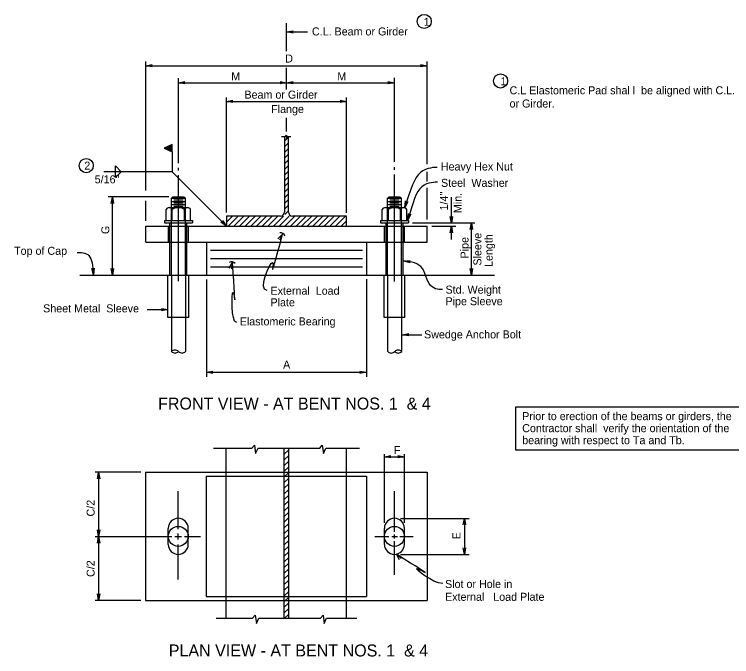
# Model space of a CAD drawing. Extents: x 113 to 232, y -103 to -27.
# Drawn here: x 116.48 to 123.95, y -74.62 to -67.93 of the extents above; entities that cross this region are included whole.
import ezdxf

# ---------------------------------------------------------------- set-up
doc = ezdxf.new("R2010")
doc.units = 0
for name, color, linetype in [('1', 7, 'Continuous'), ('B_Dimension', 7, 'Continuous'), ('B_Title Text', 7, 'Continuous')]:
    doc.layers.add(name, color=color, linetype=linetype)

msp = doc.modelspace()

# ---------------------------------------------------------------- linework, layer by layer
at = {"layer": '1'}
for p, q in [((119.3174, -68.3191), (119.3174, -68.0268)), ((119.3174, -68.118), (119.5347, -68.118)), ((117.8502, -69.7675), (117.8502, -68.4251)), ((120.7802, -69.4948), (120.7802, -68.4251)), ((117.8502, -68.4698), (120.7802, -68.4698)), ((119.3174, -68.717), (119.3174, -68.49)), ((118.1902, -69.4816), (118.1902, -68.5975)), ((120.4402, -69.4709), (120.4402, -68.5966)), ((118.1902, -68.6466), (119.3174, -68.6466)), ((119.3174, -68.6466), (120.4402, -68.6466)), ((118.6902, -69.9965), (118.6902, -68.8018)), ((119.9402, -69.9989), (119.9402, -68.8018)), ((118.6902, -68.8413), (119.9416, -68.8413)), ((119.3174, -69.1529), (119.3174, -69.0125)), ((119.307, -69.2073), (119.3149, -69.1932)), ((119.3149, -69.1932), (119.3149, -69.2263)), ((119.2635, -69.2073), (119.307, -69.2073)), ((119.2944, -69.2073), (119.2944, -69.9915)), ((119.3149, -69.2263), (119.3211, -69.2073)), ((119.3211, -69.2073), (119.3614, -69.2073)), ((119.3359, -69.9915), (119.3359, -69.2073)), ((118.1246, -69.2896), (118.0436, -69.3274)), ((118.0436, -69.3274), (118.1246, -69.365)), ((118.1246, -69.2896), (118.1246, -69.289)), ((118.1246, -69.365), (118.1246, -69.2896)), ((118.1246, -69.365), (118.1246, -69.3955)), ((118.1246, -69.3955), (118.1246, -69.5718)), ((118.1246, -69.5718), (117.4154, -69.5718)), ((117.5347, -69.6308), (117.5347, -69.5128)), ((117.5347, -69.5128), (117.5937, -69.5718)), ((117.5937, -69.5718), (117.5347, -69.6308)), ((118.6902, -70.1374), (118.1246, -69.5718)), ((118.1902, -69.5601), (118.1902, -69.5326)), ((120.4402, -69.5532), (120.4402, -69.5258)), ((120.7802, -69.6732), (120.7802, -69.5735)), ((118.1902, -70.7095), (118.1902, -69.6072)), ((120.4402, -70.7145), (120.4402, -69.6003)), ((120.7802, -70.07), (120.7802, -69.7415)), ((118.0896, -69.832), (117.4584, -69.832)), ((117.5044, -70.6479), (117.5044, -69.8355)), ((118.1336, -69.832), (118.1173, -69.8483)), ((118.1173, -69.9455), (118.1173, -69.8483)), ((118.1173, -69.8483), (118.2631, -69.8483)), ((118.1336, -69.832), (118.2468, -69.832)), ((118.1416, -69.8646), (118.2388, -69.8646)), ((118.2468, -69.832), (118.2631, -69.8483)), ((118.2631, -69.9455), (118.2631, -69.8483)), ((120.3673, -69.8483), (120.3836, -69.832)), ((120.3673, -69.8483), (120.5131, -69.8483)), ((120.3673, -69.9455), (120.3673, -69.8483)), ((120.3673, -69.8483), (120.5131, -69.8483)), ((120.3836, -69.832), (120.4968, -69.832)), ((120.3916, -69.8646), (120.4888, -69.8646)), ((120.4968, -69.832), (120.5131, -69.8483)), ((120.5131, -69.9455), (120.5131, -69.8483)), ((121.0315, -70.1065), (121.0315, -69.8375)), ((117.8502, -70.0819), (117.8502, -69.8759)), ((118.0949, -69.9455), (118.2857, -69.9455)), ((118.1173, -69.8807), (118.2631, -69.8807)), ((118.1173, -69.913), (118.2631, -69.913)), ((118.1173, -70.6479), (118.1173, -69.9455)), ((118.1416, -69.897), (118.2388, -69.897)), ((118.1416, -69.9294), (118.2388, -69.9294)), ((118.2631, -70.6479), (118.2631, -69.9455)), ((120.3449, -69.9455), (120.5357, -69.9455)), ((120.3673, -69.8807), (120.5131, -69.8807)), ((120.3673, -69.913), (120.5131, -69.913)), ((120.3673, -70.6479), (120.3673, -69.9455)), ((120.3916, -69.897), (120.4888, -69.897)), ((120.3916, -69.9294), (120.4888, -69.9294)), ((120.5131, -70.6479), (120.5131, -69.9455)), ((118.0629, -70.0793), (118.0629, -69.9638)), ((118.1272, -70.0793), (118.1272, -69.9638)), ((118.2534, -70.0793), (118.2534, -69.9638)), ((118.3179, -70.0793), (118.3179, -69.9638)), ((120.3129, -70.0793), (120.3129, -69.9638)), ((120.3772, -70.0793), (120.3772, -69.9638)), ((120.5034, -70.0793), (120.5034, -69.9638)), ((120.5679, -70.0793), (120.5679, -69.9638)), ((118.0444, -70.0793), (118.336, -70.0793)), ((118.0444, -70.0793), (118.0444, -70.1053)), ((118.336, -70.0793), (118.336, -70.1053)), ((119.2528, -70.0332), (118.6902, -70.0332)), ((118.6902, -70.0332), (118.6902, -70.1374)), ((119.9402, -70.0332), (119.3776, -70.0332)), ((119.9402, -70.1374), (119.9402, -70.0332)), ((120.2944, -70.0793), (120.586, -70.0793)), ((120.2944, -70.0793), (120.2944, -70.1053)), ((120.586, -70.0793), (120.586, -70.1053)), ((117.8502, -70.304), (117.8502, -70.1374)), ((117.8502, -70.1374), (120.7802, -70.1374)), ((118.0444, -70.1053), (118.336, -70.1053)), ((118.0861, -70.304), (118.0861, -70.1386)), ((118.1017, -70.1386), (118.1017, -70.1056)), ((118.1017, -70.304), (118.1017, -70.1386)), ((118.2787, -70.1386), (118.2787, -70.1056)), ((118.2787, -70.3039), (118.2787, -70.1386)), ((118.2943, -70.304), (118.2943, -70.1386)), ((120.2944, -70.1053), (120.586, -70.1053)), ((120.3361, -70.305), (120.3361, -70.1382)), ((120.3517, -70.1382), (120.3517, -70.1049)), ((120.3517, -70.305), (120.3517, -70.1382)), ((120.5287, -70.1382), (120.5287, -70.1059)), ((120.5287, -70.306), (120.5287, -70.1412)), ((120.5443, -70.306), (120.5443, -70.1412)), ((120.6259, -70.1053), (121.2772, -70.1053)), ((120.7802, -70.304), (120.7802, -70.1374)), ((120.828, -70.1374), (121.0771, -70.1374)), ((121.0315, -70.2774), (121.0315, -70.1398)), ((121.2394, -70.6479), (121.2394, -70.1053)), ((117.8502, -70.304), (120.7802, -70.304)), ((118.1017, -70.6479), (118.1017, -70.304)), ((118.2787, -70.6479), (118.2787, -70.3039)), ((118.4818, -70.304), (118.4818, -70.6479)), ((120.1486, -70.304), (120.1486, -70.6479)), ((120.3517, -70.6479), (120.3517, -70.305)), ((120.5287, -70.6479), (120.5287, -70.306)), ((118.5236, -70.39), (120.1068, -70.39)), ((118.5236, -70.476), (120.1068, -70.476)), ((118.5236, -70.562), (120.1068, -70.562)), ((117.1661, -70.6479), (121.4789, -70.6479)), ((118.0817, -71.0881), (118.0817, -70.6479)), ((118.1173, -70.6479), (118.1173, -71.0881)), ((118.2631, -70.6479), (118.2631, -71.0881)), ((118.2987, -71.0881), (118.2987, -70.6479)), ((120.1486, -70.6909), (120.1486, -71.7058)), ((120.3317, -71.0881), (120.3317, -70.6479)), ((120.3673, -70.6479), (120.3673, -71.0881)), ((120.5131, -70.6479), (120.5131, -71.0881)), ((120.5487, -71.0881), (120.5487, -70.6479)), ((118.4818, -70.6954), (118.4818, -71.7058)), ((117.8673, -71.0074), (118.0832, -71.0074)), ((118.2987, -71.0881), (118.0817, -71.0881)), ((118.1173, -71.0881), (118.1173, -71.4447)), ((118.2631, -71.0881), (118.2631, -71.4445)), ((120.5487, -71.0881), (120.3317, -71.0881)), ((120.3673, -71.0881), (120.3673, -71.4412)), ((120.5131, -71.0881), (120.5131, -71.4414)), ((120.52, -71.2679), (120.7227, -71.2679)), ((118.4818, -71.6581), (120.1486, -71.6581)), ((118.5555, -72.4482), (118.9549, -72.4482)), ((118.6889, -74.217), (118.6889, -72.4482)), ((119.0195, -72.4482), (119.6611, -72.4482)), ((119.2931, -74.217), (119.2931, -72.4482)), ((119.3348, -72.4482), (119.3348, -74.217)), ((119.7257, -72.4482), (120.0767, -72.4482)), ((119.9389, -74.217), (119.9389, -72.4482)), ((120.3348, -73.2242), (120.3348, -72.5116)), ((120.3348, -72.5377), (120.5431, -72.5377)), ((120.5431, -73.2242), (120.5431, -72.5116)), ((117.801, -72.6994), (117.3236, -72.6994)), ((117.3607, -72.6994), (117.3607, -73.3676)), ((117.8489, -72.6994), (117.8489, -74.0327)), ((117.8489, -72.6994), (118.6864, -72.6994)), ((118.6864, -72.6994), (119.9412, -72.6994)), ((119.9412, -72.6994), (120.7789, -72.6994)), ((119.9412, -72.6994), (120.7789, -72.6994)), ((120.7789, -72.6994), (120.7789, -74.0327)), ((118.4806, -72.7411), (118.4806, -73.9911)), ((118.4806, -72.7411), (120.1473, -72.7411)), ((120.1473, -72.7411), (120.1473, -73.9911)), ((118.1889, -73.2902), (118.1889, -72.8954)), ((120.4389, -73.3181), (120.4389, -72.8954)), ((120.5027, -73.1786), (121.2162, -73.1786)), ((121.1678, -73.1786), (121.1678, -73.5536)), ((118.0848, -73.4494), (118.0848, -73.2827)), ((118.2931, -73.4494), (118.2931, -73.2827)), ((120.3348, -73.4494), (120.3348, -73.2827)), ((120.5431, -73.4494), (120.5431, -73.2827)), ((117.3236, -73.3661), (118.1215, -73.3661)), ((117.3607, -73.3676), (117.3607, -74.0327)), ((118.1529, -73.3661), (118.2242, -73.3661)), ((118.1889, -73.3989), (118.1889, -73.3355)), ((118.2554, -73.3661), (118.2931, -73.3661)), ((118.2931, -73.3661), (118.42, -73.3661)), ((120.2352, -73.3661), (120.3794, -73.3661)), ((120.4106, -73.3661), (120.4698, -73.3661)), ((120.4389, -73.3876), (120.4389, -73.3459)), ((120.4941, -73.3661), (120.5431, -73.3661)), ((120.5431, -73.3661), (120.633, -73.3661)), ((118.1889, -73.8159), (118.1889, -73.4501)), ((120.4389, -73.767), (120.4389, -73.4171)), ((120.5027, -73.5536), (121.2162, -73.5536)), ((117.801, -74.0327), (117.3236, -74.0327)), ((117.8489, -74.0327), (118.6864, -74.0327)), ((118.4806, -73.9911), (120.1473, -73.9911)), ((118.6864, -74.0327), (119.9377, -74.0327)), ((119.9377, -74.0327), (120.7789, -74.0327)), ((118.5838, -74.2171), (118.963, -74.2171)), ((119.0276, -74.2171), (119.6691, -74.2171)), ((119.7337, -74.2171), (120.0484, -74.2171))]:
    msp.add_line(p, q, dxfattribs=at)
for points in [[(119.2996, -69.2507), (119.3308, -69.2195)], [(118.0446, -69.3278), (118.0446, -69.327)], [(118.0489, -69.3299), (118.0489, -69.325)], [(118.0532, -69.3319), (118.0532, -69.323)], [(118.0575, -69.3338), (118.0575, -69.321)], [(118.0618, -69.3358), (118.0618, -69.319)], [(118.0661, -69.3378), (118.0661, -69.317)], [(118.0704, -69.3399), (118.0704, -69.315)], [(118.0747, -69.3419), (118.0747, -69.313)], [(118.079, -69.3438), (118.079, -69.311)], [(118.0834, -69.3458), (118.0834, -69.309)], [(118.0876, -69.3478), (118.0876, -69.307)], [(118.0919, -69.3499), (118.0919, -69.305)], [(118.0963, -69.3519), (118.0963, -69.3029)], [(118.1005, -69.3538), (118.1005, -69.3009)], [(118.1049, -69.3558), (118.1049, -69.2989)], [(118.1091, -69.3578), (118.1091, -69.2969)], [(118.1134, -69.3599), (118.1134, -69.295)], [(118.1178, -69.3619), (118.1178, -69.2929)], [(118.122, -69.3638), (118.122, -69.2909)], [(119.2996, -69.3096), (119.3308, -69.2785)], [(119.2996, -69.3685), (119.3308, -69.3374)], [(119.2996, -69.4275), (119.3308, -69.3963)], [(119.2996, -69.4864), (119.3308, -69.4552)], [(119.2996, -69.5453), (119.3308, -69.5141)], [(119.2996, -69.6042), (119.3308, -69.573)], [(119.2996, -69.6631), (119.3308, -69.632)], [(119.2996, -69.722), (119.3308, -69.6909)], [(119.2996, -69.781), (119.3308, -69.7498)], [(119.2996, -69.8399), (119.3308, -69.8087)], [(119.2996, -69.8988), (119.3308, -69.8676)], [(119.2996, -69.9577), (119.3308, -69.9265)], [(119.2996, -70.0166), (119.3308, -69.9855)], [(118.6902, -70.0958), (118.7528, -70.0332)], [(118.6902, -70.0369), (118.6939, -70.0332)], [(118.7075, -70.1374), (118.8117, -70.0332)], [(118.7664, -70.1374), (118.8706, -70.0332)], [(118.8254, -70.1374), (118.9295, -70.0332)], [(118.8843, -70.1374), (118.9884, -70.0332)], [(118.9432, -70.1374), (119.0474, -70.0332)], [(119.0021, -70.1374), (119.1063, -70.0332)], [(119.061, -70.1374), (119.1652, -70.0332)], [(119.1199, -70.1374), (119.2242, -70.0332)], [(119.1789, -70.1374), (119.2831, -70.0332)], [(119.2379, -70.1374), (119.342, -70.0332)], [(119.2968, -70.1374), (119.4009, -70.0332)], [(119.3557, -70.1374), (119.4599, -70.0332)], [(119.4146, -70.1374), (119.5188, -70.0332)], [(119.4735, -70.1374), (119.5777, -70.0332)], [(119.5324, -70.1374), (119.6367, -70.0331)], [(119.5914, -70.1374), (119.6955, -70.0332)], [(119.6504, -70.1373), (119.7544, -70.0332)], [(119.7092, -70.1374), (119.8134, -70.0332)], [(119.7682, -70.1374), (119.8724, -70.0332)], [(119.8271, -70.1374), (119.9313, -70.0332)], [(119.886, -70.1374), (119.9402, -70.0832)], [(118.2009, -70.1374), (118.2009, -70.1374)], [(118.3188, -70.1374), (118.3188, -70.1374)], [(118.3778, -70.1374), (118.3778, -70.1374)], [(120.3336, -70.1374), (120.3336, -70.1374)], [(118.9549, -72.4482), (118.9823, -72.4157), (118.9944, -72.5025), (119.0195, -72.4482)], [(119.2931, -72.5102), (119.3348, -72.4686)], [(119.6611, -72.4482), (119.6884, -72.4157), (119.7005, -72.5025), (119.7257, -72.4482)], [(119.2931, -72.5691), (119.3348, -72.5276)], [(119.2931, -72.6281), (119.3348, -72.5865)], [(119.2931, -72.6871), (119.3348, -72.6454)], [(119.2931, -72.746), (119.3348, -72.7044)], [(119.2931, -72.8049), (119.3348, -72.7633)], [(119.2931, -72.8638), (119.3348, -72.8222)], [(119.2931, -72.9227), (119.3348, -72.8811)], [(119.2931, -72.9816), (119.3348, -72.9401)], [(119.2931, -73.0406), (119.3348, -72.999)], [(119.2931, -73.0995), (119.3348, -73.0579)], [(119.2931, -73.1585), (119.3348, -73.1168)], [(119.2931, -73.2174), (119.3347, -73.1758)], [(119.2931, -73.2763), (119.3348, -73.2347)], [(119.2931, -73.3352), (119.3348, -73.2936)], [(119.2931, -73.3941), (119.3348, -73.3526)], [(119.2931, -73.4531), (119.3348, -73.4115)], [(119.2931, -73.512), (119.3348, -73.4704)], [(119.2931, -73.5709), (119.3348, -73.5293)], [(119.2931, -73.6298), (119.3348, -73.5882)], [(119.2931, -73.6888), (119.3348, -73.6471)], [(119.2931, -73.7477), (119.3348, -73.7061)], [(119.2931, -73.8066), (119.3348, -73.7651)], [(119.2931, -73.8656), (119.3348, -73.824)], [(119.2931, -73.9245), (119.3348, -73.8829)], [(119.2931, -73.9834), (119.3348, -73.9418)], [(119.2931, -74.0423), (119.3348, -74.0007)], [(119.2931, -74.1012), (119.3348, -74.0596)], [(119.2931, -74.1601), (119.3348, -74.1186)], [(118.963, -74.2171), (118.9904, -74.1846), (119.0024, -74.2713), (119.0276, -74.2171)], [(119.2931, -74.2191), (119.3348, -74.1775)], [(119.6691, -74.2171), (119.6964, -74.1846), (119.7085, -74.2713), (119.7337, -74.2171)]]:
    msp.add_lwpolyline(points, dxfattribs=at)
msp.add_lwpolyline([(121.704, -72.0181), (124.6449, -72.0181), (124.6449, -72.4691), (121.704, -72.4691)], close=True, dxfattribs=at)
for centre, radius in [((120.7486, -68.0083), 0.0733), ((121.5436, -68.6281), 0.0733), ((117.232, -69.509), 0.0733), ((118.189, -73.3661), 0.1042), ((120.439, -73.3661), 0.1042)]:
    msp.add_circle(centre, radius, dxfattribs=at)
for centre, radius, start, end in [((118.095, -69.9829), 0.0375, 30.80861, 149.1914), ((118.1903, -70.0635), 0.118, 57.68982, 122.31018), ((118.2857, -69.9831), 0.0376, 30.95728, 149.04272), ((120.345, -69.9829), 0.0375, 30.80861, 149.1914), ((120.4403, -70.0635), 0.118, 57.68982, 122.31018), ((120.5357, -69.9831), 0.0376, 30.95728, 149.04272), ((119.2528, -69.9915), 0.0417, 270, 360), ((119.3776, -69.9915), 0.0417, 180, 270), ((119.2538, -70.2589), 0.0513, 21.6992, 99.92259), ((118.7437, -70.5617), 0.0513, 40.39617, 118.61956), ((118.1553, -71.4778), 0.0504, 43.71346, 136.28654), ((120.4783, -71.4778), 0.0504, 43.71346, 136.28654), ((118.1553, -71.4081), 0.0504, 223.71346, 316.28654), ((118.2283, -71.4081), 0.0504, 223.71346, 316.28654), ((120.4053, -71.4081), 0.0504, 223.71346, 316.28654), ((120.4783, -71.4081), 0.0504, 223.71346, 316.28654), ((118.189, -73.2827), 0.1042, 0, 180), ((120.439, -73.2827), 0.1042, 0, 180), ((118.189, -73.4494), 0.1042, 180, 0), ((120.439, -73.4494), 0.1042, 180, 0)]:
    msp.add_arc(centre, radius, start, end, dxfattribs=at)
for points in [[(120.8851, -69.5282), (120.8684, -69.5276), (120.6813, -69.5246), (120.6105, -69.7447), (120.5459, -69.9454)], [(120.8883, -69.6821), (120.8719, -69.6815), (120.6946, -69.6749), (120.6335, -69.884), (120.5791, -70.0756)], [(119.1151, -70.8083), (119.0132, -70.8083), (119.2755, -70.2226), (119.1151, -70.8083), (119.2755, -70.2226)], [(117.1355, -70.4135), (117.171, -70.4108), (117.285, -70.4114), (117.2978, -70.5479), (117.3069, -70.6446)], [(118.7948, -71.1404), (118.7365, -71.1369), (118.753, -70.5158), (118.7948, -71.1404), (118.753, -70.5158)], [(120.9399, -70.7982), (120.923, -70.7994), (120.7855, -70.8055), (120.7505, -70.5129), (120.58, -70.5056), (120.5348, -70.5037)], [(120.9419, -73.8563), (120.834, -73.8533), (120.4588, -73.5497), (120.9419, -73.8563), (120.4588, -73.5497)]]:
    msp.add_open_spline(points, degree=3, dxfattribs=at)
at = {"layer": 'B_Dimension'}
for points in [[(119.3857, -68.13), (119.3174, -68.118), (119.3857, -68.1059)], [(117.9185, -68.4819), (117.8502, -68.4698), (117.9185, -68.4578)], [(120.7119, -68.4578), (120.7802, -68.4698), (120.7119, -68.4819)], [(118.2585, -68.6586), (118.1902, -68.6466), (118.2585, -68.6345)], [(119.249, -68.6345), (119.3174, -68.6466), (119.249, -68.6586)], [(119.3857, -68.6586), (119.3174, -68.6466), (119.3857, -68.6345)], [(120.3719, -68.6345), (120.4402, -68.6466), (120.3719, -68.6586)], [(118.7585, -68.8533), (118.6902, -68.8413), (118.7585, -68.8292)], [(119.8733, -68.8292), (119.9416, -68.8413), (119.8733, -68.8533)], [(117.4924, -69.9039), (117.5044, -69.8355), (117.5165, -69.9039)], [(120.5783, -69.8841), (120.5459, -69.9454), (120.5553, -69.8767)], [(120.6094, -70.0131), (120.5791, -70.0756), (120.5862, -70.0066)], [(118.6504, -70.0805), (118.6902, -70.1374), (118.6334, -70.0976)], [(121.0436, -70.0381), (121.0315, -70.1065), (121.0195, -70.0381)], [(121.0195, -70.2081), (121.0315, -70.1398), (121.0436, -70.2081)], [(121.2274, -70.1736), (121.2394, -70.1053), (121.2515, -70.1736)], [(119.224, -70.2691), (119.2755, -70.2226), (119.243, -70.2839)], [(118.7193, -70.5764), (118.753, -70.5158), (118.742, -70.5843)], [(120.6026, -70.5186), (120.5348, -70.5037), (120.6036, -70.4946)], [(117.3125, -70.5755), (117.3069, -70.6446), (117.2885, -70.5777)], [(117.5165, -70.5796), (117.5044, -70.6479), (117.4924, -70.5796)], [(121.2515, -70.5796), (121.2394, -70.6479), (121.2274, -70.5796)], [(118.0149, -70.9954), (118.0832, -71.0074), (118.0149, -71.0195)], [(120.5883, -71.2799), (120.52, -71.2679), (120.5883, -71.2558)], [(118.5501, -71.6702), (118.4818, -71.6581), (118.5501, -71.6461)], [(120.0802, -71.6461), (120.1486, -71.6581), (120.0802, -71.6702)], [(120.4031, -72.5498), (120.3348, -72.5377), (120.4031, -72.5257)], [(120.4748, -72.5257), (120.5431, -72.5377), (120.4748, -72.5498)], [(117.3486, -72.7677), (117.3607, -72.6994), (117.3727, -72.7677)], [(121.1557, -73.2469), (121.1678, -73.1786), (121.1798, -73.2469)], [(117.3727, -73.2993), (117.3607, -73.3676), (117.3486, -73.2993)], [(117.3486, -73.436), (117.3607, -73.3676), (117.3727, -73.436)], [(121.1798, -73.4852), (121.1678, -73.5536), (121.1557, -73.4852)], [(120.4915, -73.6109), (120.4588, -73.5497), (120.5104, -73.596)], [(117.3727, -73.9644), (117.3607, -74.0327), (117.3486, -73.9644)]]:
    msp.add_lwpolyline(points, dxfattribs=at)

# ---------------------------------------------------------------- texts
at = {"layer": '1'}
for s, height, p in [('1', 0.0833, (120.7446, -68.054)), ('C.L. Beam or Girder', 0.083334, (119.5804, -68.1545)), ('D', 0.0833, (119.3029, -68.4363)), ('M', 0.0833, (118.7408, -68.6215)), ('M', 0.0833, (119.8447, -68.6215)), ('1', 0.0833, (121.5427, -68.6727)), ('C.L Elastomeric Pad shal l  be aligned with C.L. Beam', 0.083334, (121.6372, -68.7669)), ('Beam or Girder', 0.083334, (118.8781, -68.8118)), ('or Girder.', 0.08333, (121.6372, -68.9044)), ('Flange', 0.08333, (119.1562, -68.9618)), ('2', 0.0833, (117.2111, -69.5505)), ('Heavy Hex Nut', 0.083334, (120.9222, -69.5597)), ("5/16''", 0.08333, (117.3195, -69.6932)), ('Steel  Washer', 0.083334, (120.9238, -69.7297)), ('Top of Cap', 0.08333, (116.4808, -70.437)), ('External  Load ', 0.083334, (119.1493, -70.8522)), ('Std. Weight ', 0.083334, (120.9707, -70.8406)), ('Plate', 0.08333, (119.1493, -70.973)), ('Pipe Sleeve', 0.083334, (120.9707, -70.9614)), ('Sheet Metal  Sleeve', 0.083334, (116.7832, -71.0358)), ('Elastomeric Bearing', 0.083334, (118.8289, -71.1712)), ('Swedge Anchor Bolt', 0.083334, (120.7473, -71.3065)), ('A', 0.0833, (119.2804, -71.6206)), ('Prior to erection of the beams or girders, the ', 0.083334, (121.7688, -72.1572)), ('Contractor shall  verify the orientation of the ', 0.083334, (121.7688, -72.2822)), ('bearing with respect to Ta and Tb.', 0.083334, (121.7688, -72.4072)), ('F', 0.0833, (120.4336, -72.5106)), ('Slot or Hole in', 0.083334, (120.9658, -73.9034)), ('External   Load Plate', 0.083334, (120.9658, -74.0367))]:
    msp.add_text(s, height=height, dxfattribs=at).set_placement(p)
for s, height, p in [("1/4''", 0.08333, (120.9961, -69.9758)), ('Min.', 0.08333, (121.1385, -70.0028)), ('G', 0.0833, (117.4719, -70.2208)), ('Sleeve ', 0.08333, (121.3439, -70.5485)), ('Length', 0.08333, (121.4614, -70.5632)), ('Pipe', 0.08333, (121.2099, -70.4744)), ('C/2', 0.08333, (117.319, -73.1594)), ('E', 0.0833, (121.1261, -73.3974)), ('C/2', 0.08333, (117.319, -73.7886))]:
    msp.add_text(s, height=height, rotation=90, dxfattribs=at).set_placement(p)
at = {"layer": 'B_Title Text'}
for s, p in [('FRONT VIEW - AT BENT NOS. 1  & 4', (117.9791, -72.0469)), ('PLAN VIEW - AT BENT NOS. 1  & 4', (118.0906, -74.6159))]:
    msp.add_text(s, height=0.124834, dxfattribs=at).set_placement(p)

doc.saveas('drawing.dxf')
